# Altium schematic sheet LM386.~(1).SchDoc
size A4
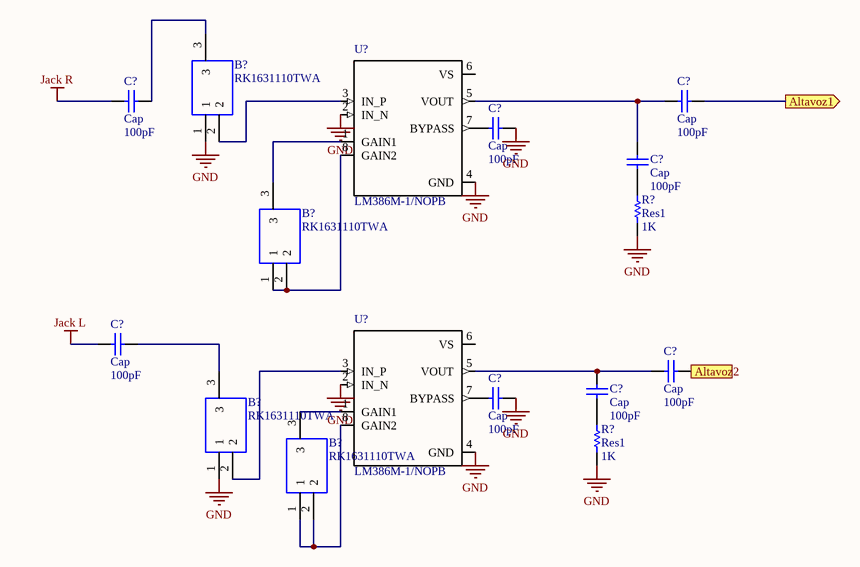
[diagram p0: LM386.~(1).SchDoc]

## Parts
(Parts that share a designator on the sheet are numbered #1, #2 ... from top to bottom, then left to right.)
B?#1  RK1631110TWA  [RK1631110TWA]
B?#2  RK1631110TWA  [RK1631110TWA]
B?#3  RK1631110TWA  [RK1631110TWA]
B?#4  RK1631110TWA  [RK1631110TWA]
C?#1  Cap  value 100pF  [RAD-0.3]
C?#2  Cap  value 100pF  [RAD-0.3]
C?#3  Cap  value 100pF  [RAD-0.3]
C?#4  Cap  value 100pF  [RAD-0.3]
C?#5  Cap  value 100pF  [RAD-0.3]
C?#6  Cap  value 100pF  [RAD-0.3]
C?#7  Cap  value 100pF  [RAD-0.3]
C?#8  Cap  value 100pF  [RAD-0.3]
R?#1  Res1  value 1K  [AXIAL-0.3]
R?#2  Res1  value 1K  [AXIAL-0.3]
U?#1  LM386M-1/NOPB  [SOIC127P600X175-8N]
U?#2  LM386M-1/NOPB  [SOIC127P600X175-8N]

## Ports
Altavoz1 (out), Altavoz2 (out)

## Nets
GND: B?#1.1 B?#3.1 C?#3.1 C?#7.2 R?#1.1 R?#2.1 U?#1.2(IN_N) U?#1.4(GND) U?#2.2(IN_N) U?#2.4(GND)
Jack L: C?#5.2
Jack R: C?#2.2
Altavoz1: C?#1.2 ; port Altavoz1
Altavoz2: C?#6.2 ; port Altavoz2
NetB?#1_2: B?#1.2 U?#1.3(IN_P)
NetB?#1_3: B?#1.3 C?#2.1
NetB?#2_1: B?#2.1 B?#2.2 U?#1.8(GAIN2)
NetB?#2_3: B?#2.3 U?#1.1(GAIN1)
NetB?#3_2: B?#3.2 U?#2.3(IN_P)
NetB?#3_3: B?#3.3 C?#5.1
NetB?#4_1: B?#4.1 B?#4.2 U?#2.8(GAIN2)
NetB?#4_3: B?#4.3 U?#2.1(GAIN1)
NetC?#1_1: C?#1.1 C?#4.2 U?#1.5(VOUT)
NetC?#3_2: C?#3.2 U?#1.7(BYPASS)
NetC?#4_1: C?#4.1 R?#1.2
NetC?#6_1: C?#6.1 C?#8.2 U?#2.5(VOUT)
NetC?#7_1: C?#7.1 U?#2.7(BYPASS)
NetC?#8_1: C?#8.1 R?#2.2

Not connected (* = marked no-connect by the designer): U?#1 6(VS); U?#2 6(VS)

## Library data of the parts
B?#1-B?#4 = RK1631110TWA: Carbon Film Potentiometer RK163 Series with a 6 mm Dia. Shaft 10k 20% 0.1W; Manufacturer_Name: ALPS
C?#1-C?#8 = Cap: Capacitor
R?#1 R?#2 = Res1: Resistor
U?#1 U?#2 = LM386M-1/NOPB: Wide Input Voltage Low Power Audio Amplifier with Internal Gain 8-SOIC 0 to 70; MF: Texas Instruments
